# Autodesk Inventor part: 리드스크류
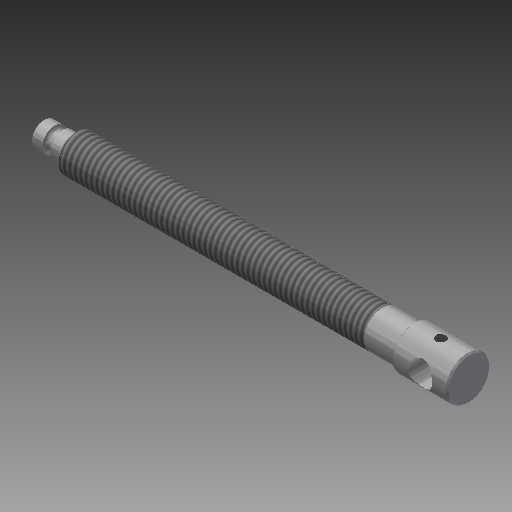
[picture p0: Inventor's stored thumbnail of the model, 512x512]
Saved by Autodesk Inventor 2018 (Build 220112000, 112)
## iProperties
Created: 2019-04
Part Number: 리드스크류
Material: 강철, 연강
Document SubType Name: Modeling
Designer: mduedu
Density: 1 g/cm^3
Appearance: 강철
Author: mduedu
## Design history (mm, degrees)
sketch "스케치1"
  geometry: C1 r 6 at (0, 0); 1 further point
  constraints: 1 centre point, 1 coincident
  dimensions: "d0" = 12 diameter of C1
extrude "돌출1" new body sketch "스케치1" distance "d1" = 110; taper "d2" = 0 deg
sketch "스케치2"
  geometry: C1 r 4 at (0, 0); 1 further point
  constraints: 1 centre point, 1 coincident
  dimensions: "d3" = 8 diameter of C1
extrude "돌출2" join sketch "스케치2" distance "d4" = 10; taper "d5" = 0 deg
sketch "스케치3"
  geometry: C1 r 7 at (0, 0); 1 further point
  constraints: 1 centre point, 1 coincident
  dimensions: "d9" = 14 diameter of C1
extrude "돌출3" join sketch "스케치3" distance "d10" = 18; taper "d11" = 0 deg
feature "스레드1" dims "d12" = 100, "d13" = 0
chamfer "모따기2" distance "d14" = 1; stored, may be unused: second distance "d15" = 2, angle "d16" = 45 deg
chamfer "모따기3" distance "d17" = 0.5; stored, may be unused: second distance "d18" = 2, angle "d19" = 45 deg
chamfer "모따기4" distance "d20" = 0.5; stored, may be unused: second distance "d21" = 2, angle "d22" = 45 deg
sketch "스케치4"
  geometry: L1 (-110, -5)-(-110, 5) reference; L2 (-119.5, 4)-(-119.5, -4) reference; L3 (-119.5, 0)-(-110, 0); C1 r 1.25 at (-115, 4); 1 further point
  constraints: 2 end point, 2 midpoint, 1 centre point
  dimensions: "d23" = 2.5 diameter of C1; "d24" = 5 distance from line of C1.centre L1; "d25" = 4 distance from line of C1.centre L3
revolve "회전1" sketch "스케치4" stored, may be unused: angle "d26" = 90 deg
sketch "스케치5"
  geometry: L1 (0, -6.5)-(0, 6.5) reference; C1 r 4 at (9, 0); 2 further points
  constraints: 1 centre point, 1 horizontal alignment, 1 midpoint
  dimensions: "d27" = 8 diameter of C1; "d28" = 9 distance from line of C1.centre L1
extrude "돌출4" cut sketch "스케치5" extent not by distance; stored distance "d29" = 15; taper "d30" = 0 deg
node "작업 평면1"
sketch "스케치6"
  geometry: L1 (0, 6.5)-(0, -6.5) reference; 2 further points
  constraints: 1 horizontal alignment
  dimensions: "d31" = 9 distance from line of point (-9, 0) L1
hole "구멍1" sketch "스케치6" at (-9, 0) diameter "d32" = 3.242; stored, may be unused: countersink angle "d36" = 90 deg, drill point angle "d38" = 118 deg; dims "d33" = 6, "d34" = 4, "d35" = 2, "d37" = 8
node "솔리드1"
